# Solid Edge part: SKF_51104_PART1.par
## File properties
Title: SKF_51104_PART1
Author: psAdmin
Comments: Thrust ball bearings, single direction
Template: iso metric part.par
Last saved by: psAdmin
Revision: 1
Application: Solid Edge
Document Number: SKF_51104_PART1
Company: SKF
Density: 4,84668224983e+04 kg/m^3
Accuracy: 0,990
NB: SKF_51104_PART1
NT: Thrust ball bearings, single direction
NBSYN: SKF_$TC._PART1
LINA: SKF_51104_PART1
CATALOG: SKF
DESIGNATION: 51104
WASHER: No seat washer
DD: 20.0
D: 35.0
H: 10.00
LOAD1: 15.1
LOAD2: 29.0
LOAD3: 1.1
SPEED1: 7500
SPEED2: 10000
BEARING: 51104
SUPPLIER: SKF
ARTICLENO: SKF_51104_PART1
BOMINFO: SKF_51104_PART1
CREATOR: CADENAS GmbH
ID: skf:SKF_51104_PART1
CADENASIDSTR: DOCATTR{IDENT{"{$CADENAS_DATA/23d-libs/skf/bearings_units_and_housings/ball_bearings/thrust_ball_bearings/bd1_001_bdc_001.prj},207 {VTYP=3D},{NB=SKF_51104_PART1},{LINA=SKF_51104_PART1},{NN=BD1_001_BDC_001_PART1},{NOPRJ=TRUE},{DATE=08.09.2023 08:50:36},{GEOMDATE=04.09.2023 08:34:44},{VERSION=},{LINEID=46530},{WBVAR=WASHER},{WBNUMERIC=}  {NB=SKF_51104_PART1},{LINA=SKF_51104_PART1},{KT=DUMMY},{DESIGNATION=51104},{WASHER=},{DD=20.0},{D=35.0},{DX=},{DXX=MIN},{H=10.00},{H1=},{DD1=35.00},{D1=21.00},{D2=},{D3=},{C=},{R=},{SS=},{R12=0.3},{PITCH=27.500},{DW=5.556},{ALPHA=90},{DAMIN=29.00},{DAMAX=26.00},{RAMAX=0.30},{LOAD1=15.1},{LOAD2=29.0},{LOAD3=1.1},{SPEED1=7500},{SPEED2=10000},{A=0.0044},{Z=14},{II=1},{MASS=0.03700},{BEARING=51104},{WASHERVAR=},{POPULAR=Yes},{XHO=7.2224},{BHO=2.7776},{BSH=2.7776},{Y3=0},{H3=0},{B3=0},{WASHERALG='','No seat washer'},{WSPN=},{DESIGN=tbb1},{H1ALG=0},{SSALG=0},{RALG=0},{TC=51104},{DXA=35.000}"}}
Username: psAdmin
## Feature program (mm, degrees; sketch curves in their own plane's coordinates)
sketch for "unnamed RevolvedProtrusion 1" plane through (0, 0, 0) normal (0, 0, 1) x-axis (1, 0, 0)
revolve "unnamed RevolvedProtrusion 1" add finite 360 deg about sketch line (6.389, 0) -> (3.611, 0)
sketch for "Hole_1" plane through (0, 13.75, 0) normal (1, 0, 0) x-axis (0, -1, 0)
  hole centre (0, 0) bore radius 2.778
hole "Hole_1" diameter 5.556 finite
pattern "unnamed Pattern 1" of "Hole_1"
hole "unnamed Hole 1" finite
hole "unnamed Hole 2" finite
hole "unnamed Hole 3" finite
hole "unnamed Hole 4" finite
hole "unnamed Hole 5" finite
hole "unnamed Hole 6" finite
hole "unnamed Hole 7" finite
hole "unnamed Hole 8" finite
hole "unnamed Hole 9" finite
hole "unnamed Hole 10" finite
hole "unnamed Hole 11" finite
hole "unnamed Hole 12" finite
hole "unnamed Hole 13" finite
Other named dimensions: "CoordinateSystem_2": Z_Rotation = -90 deg; Y_Translation = 13.75 mm | "CoordinateSystem_3": Y_Rotation = 90 deg
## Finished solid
Body 1: solid body, 20 faces, 34 edges, 0 vertices.
  Faces by surface: cylinder 16, plane 2, torus 2
  Edges by curve: circle 34
Bounding box of the edges (mm; curved faces can reach further): 2.778 x 35.000 x 35.000, from (3.611, -17.5, -17.5) to (6.389, 17.5, 17.5).
Cylindrical faces by radius (mm): R2.778 x14, R10.5 x1, R17.5 x1
Toroidal faces (ring radius, tube radius in mm): R17.2 r0.3 x2
Planar faces by outward normal: +x 1, -x 1
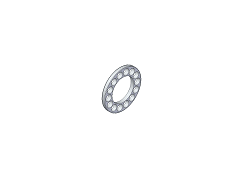
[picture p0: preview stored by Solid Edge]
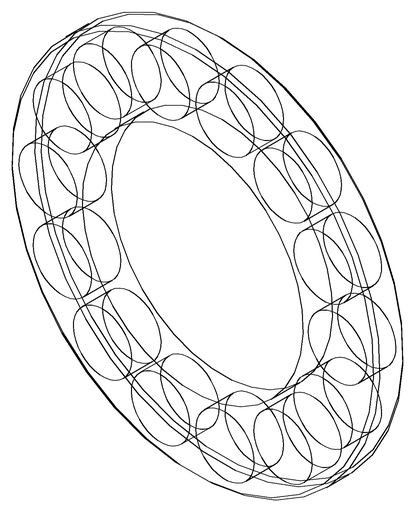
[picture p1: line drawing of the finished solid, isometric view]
